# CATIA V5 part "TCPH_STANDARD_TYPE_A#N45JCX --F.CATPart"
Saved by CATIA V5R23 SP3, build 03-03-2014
Part number: TCPH_STANDARD_TYPE_A#N45JBE
Revision: --F
Nomenclature: _
Description: TCPH_STANDARD_TYPE_A
Property "MAT": "PR"
Property "Long Description": "CRYOP_HOUSING_UPPER_POSITION_C+GS"
Property "PBS Short": "3.1"
Property "VAC & FUEL CLASS": "N"
Property "GAS CLASS": "N"
Property "WATER CLASS": "N"
Property "ELEC CLASS": "N"
Property "CODAC CLASS": "N"
Property "RH CLASS": "N"
Property "HEAT CLASS": "N"
Property "DIAG CLASS": "N"
Property "CRYO CLASS": "N"
Property "NEU CLASS": "N"
Property "ASSY CLASS": "N"
Property "SAFETY CLASS": "N"
Property "QA CLASS": "N"
Property "DEPT": "_"
Property "DIVN": "_"
Property "GROUP": "_"
Property "UNIT": "_"
Property "PARTY": "_"
Property "RO": "---"
Property "RE": "SEKACHI"
Property "PRO": "---"
Property "Part Code": "TXT1"
Property "Part Origin": "ITER-P-3282KS+AA+-0"
Property "ITER Part Version": "-1"
Property "PBS Full Meaning": "VACUUM PUMPING"
Property "Date": "2005-11-11-09.18.13.000000"
Property "Responsible": "GLISSC"
Property "Site Resp": "SITE_AA"
Property "Organization": "ITER"
Property "Former PN": "ITER-P-3282KS"
Property "CHK MAT": "UNSYNC"
Property "PBS": "3.1 VACUUM PUMPING"
Property "Sig. Point Calc.": "N"
Property "ShortDescMig": "CRYOP_HOUSING_UPPER"
Property "PbsLevel1Mig": "31"
Property "PNMig": "235NFX"
Property "User In Enovia": "VAUQUEJ"
Property "Life Cycle Status": "Approved"
Property "ID": "N45JBE"
Property "AT": "PD"
Property "PBS 1": "24"
Property "PBS 2": "CR"
Property "PBS 3": "LC"
Property "LONG": "-"
Property "PREF": "Y"
Property "Change Type": "Minor"
Property "Maturity Level": "CD"
Property "Export Number": "_"
Property "REP": "CM"
Property "Object Type": "_"
Property "CADENAS_ID": "_"
Property "Description Modification": "DR-34 and DR-35"
Property "Description Documents": "_"
Property "BOM": "_"
Property "External Part ID": "ITER-C-235NEF"
Material "Stainless steel": density 8030 kg/m3, Young's modulus 2e+11 Pa, Poisson ratio 0.266, thermal expansion 1.17e-05 1/K
Bounding box of the stored display mesh (mm): x 13380 to 16870, y -1350 to 1350, z -6313 to -2983
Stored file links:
  C:\Users\pandeym\Desktop\__TCPH\TCPH_STANDARD_TYPE_A#N45JCX --F.CATPart
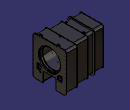
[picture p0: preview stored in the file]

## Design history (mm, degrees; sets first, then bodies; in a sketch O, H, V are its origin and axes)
Set1
  Line1 "CRYOPUMP_CENTER_AXIS": linked copy from another document
  DatumSurface1 "SURFACE_IN": linked copy from another document
  DatumSurface2 "SURFACE_OUT": linked copy from another document
  Sketch1 "TCPH_INNER_CYLINDER", origin (0, 0, 0), H (-1, 0, 0), V (0, 0, 1), geometry linked from another document
  Sketch2 "TCPH_VACUUM_PUMP_INTERFACE", origin (0, 0, 0), H (-1, 0, 0), V (0, 0, 1), geometry linked from another document
  Plane1 "CRYOPUMP_INTERFACE_PLANE_02": linked copy from another document
  Plane2 "CRYOPUMP_INTERFACE_PLANE_03": linked copy from another document
  Plane3 "CRYOPUMP_INTERFACE_PLANE_04": linked copy from another document
  Sketch3 "RH_RAIL_POCKETS", origin (15875, 0, 0), H (0, 1, 0), V (0, 0, 1), geometry linked from another document
  Sketch4 "CRYOPUMP_HOLES", origin (16720, 0, 0), H (0, 1, 0), V (0, 0, 1), geometry linked from another document
  Plane4 "CRYOPUMP_INTERFACE_PLANE_09": linked copy from another document
  Plane5 "CRYOPUMP_INTERFACE_PLANE_10": linked copy from another document
  Plane6 "CRYOPUMP_INTERFACE_PLANE_08": linked copy from another document
  Plane7 "CRYOPUMP_INTERFACE_PLANE_07": linked copy from another document
  Sketch5 "INNER_PLATES_HOLES", origin (15875, 0, 0), H (0, 1, 0), V (0, 0, 1), geometry linked from another document
  Sketch6 "SOCKET_PROFIL", origin (15540, 0, 0), H (0, 1, 0), V (0, 0, 1), geometry linked from another document
  Sketch7 "TCPH_SHELL_03", origin (14800, 0, 0), H (0, 1, 0), V (0, 0, 1), geometry linked from another document
  Sketch8 "TCPH_SHELL_02", origin (15855, 0, 0), H (0, 1, 0), V (0, 0, 1), geometry linked from another document
  Sketch9 "TCPH_SHELL_01", origin (16750, 0, 0), H (0, 1, 0), V (0, 0, 1), geometry linked from another document
  Sketch10 "TCPH_SHELL_04", origin (13400, 0, 0), H (0, 1, 0), V (0, 0, 1), geometry linked from another document
  Sketch11 "VERTICAL_PLATE_02", origin (14820, 0, 0), H (0, 1, 0), V (0, 0, 1), geometry linked from another document
  Sketch12 "VERTICAL_PLATE_01", origin (15855, 0, 0), H (0, 1, 0), V (0, 0, 1), geometry linked from another document
  Sketch13 "VERTICAL_PLATES_03", origin (13380, 0, 0), H (0, 1, 0), V (0, 0, 1), geometry linked from another document
  Sketch14 "INTERFACE_PLATE", origin (16800, 0, 0), H (0, 1, 0), V (0, 0, 1), geometry linked from another document
  Sketch15 "TCPH_FLANGE", origin (14800, 0, 0), H (0, 1, 0), V (0, 0, 1), geometry linked from another document
  DatumCurve1 "MONITORING_PIPE_PROFIL": linked copy from another document
  Sketch16 "LIFTING_PADS", origin (0, 0, -3193), H (1, 0, 0), V (0, 1, 0), geometry linked from another document
  Sketch17 "LIFTING_PADS_HOLES", origin (0, 0, -3193), H (1, 0, 0), V (0, 1, 0), geometry linked from another document
  Sketch18 "TEMPORARY_FLANGE_HOLES", origin (16800, 0, 0), H (0, 1, 0), V (0, 0, 1), geometry linked from another document
  Sketch19 "VACUUM_PIPE_SECTION_1", origin (0, 0, -6293), H (1, 0, 0), V (0, 1, 0), geometry linked from another document
  Sketch20 "RH_RAILS_HOLES", origin (16830, 0, 0), H (0, 1, 0), V (0, 0, 1), geometry linked from another document
  Sketch21 "RH_PINS", origin (15875, 0, 0), H (0, 1, 0), V (0, 0, 1), geometry linked from another document
  Sketch22 "RH_RAILS_INTERFACE", origin (16830, 0, 0), H (0, 1, 0), V (0, 0, 1), geometry linked from another document
  Sketch23 "PIS_TCPH_HOLES", origin (13380, 0, 0), H (0, 1, 0), V (0, 0, 1), geometry linked from another document
  Sketch24 "PIS_TCPH_PIPES", origin (13380, 0, 0), H (0, 1, 0), V (0, 0, 1), geometry linked from another document
  Sketch25 "FLANGE_DOCKING_PINS", origin (16800, 0, 0), H (0, 1, 0), V (0, 0, 1), geometry linked from another document
  Plane8 "TCPH_FRONT_LIMIT_PLANE_1": linked copy from another document
Set2
  Extract1: ExtractElem end face of Pad14
  Extract2: ExtractElem face of Pad14
  Extract3: ExtractElem face of Pad14
  Extract4: ExtractElem face of Pad14
  Join1: Elements (Extract1; Extract2; Extract3; Extract4)
Body1 "SHELL" (main body)
  Pad1: profile Sketch8, direction (1, 0, 0), up to start face of Pad9, opposite side up to Plane3
  Pad2: profile Sketch7, direction (1, 0, 0), up to DatumSurface2
  Pad3: profile Sketch9, direction (1, 0, 0), up to Plane2, opposite side up to end face of Pad5
  Pad4: profile Sketch10, direction (1, 0, 0), up to DatumSurface1
  Body2 "FLANGE"
    Solid1: linked copy from another document
  Remove1: tool Body2
  Sketch26 on face of Pad1, origin (0, 0, -6213), H (1, 0, 0), V (0, -1, 0)
    projected circle E1 centre (15565, 780) radius 77.04 from edge of Sketch19
  Pocket1: profile Sketch26, direction (0, 0, 1), through (limit type 6)
  Split1: SplitPlane Join1
Body3 "INTERFACE_PLATE"
  Pad5: profile Sketch14, direction (1, 0, 0), up to Plane1
  Shaft1: profile Sketch2, axis axis of face of Shaft2, angle 360
  Pad6: profile Sketch25, direction (1, 0, 0), length 70
  Chamfer1: length 15, angle 30, on edge [face of Pad6 | end face of Pad6] (x2)
  Sketch27 on face of Shaft1, origin (16800, -579.3117, -3160), H (0, 1, 0), V (0, 0, 1)
    point P1 (579.3117, -3)
    reference projected point E1 (579.3117, -3) from vertex of Sketch18
    coincidence: P1 E1
  Hole1: placed by Sketch27, at (16800, 0, -3163) direction (-1, 0, 0), diameter 22, through (limit type 3)
  UserPattern1: of Hole1, copies 49, at the points of Sketch18
  Sketch28 on face of Shaft1, origin (16720, -88.6401, -3549.6454), H (0, 1, 0), V (0, 0, 1)
    point P1 (-759.3599, -843.3546)
    reference projected point E1 (-759.3599, -843.3546) from vertex of Sketch4
    coincidence: E1 P1
  Hole2: placed by Sketch28, at (16720, -848, -4393) direction (-1, 0, 0), diameter 20.752, depth 80, V-bottom angle 120, threaded "M24", thread diameter 24, thread depth 70, pitch 3
  UserPattern2: of Hole2, copies 61, at the points of Sketch4
  Pocket2: profile Sketch23, direction (-1, 0, 0), up to face of Shaft1
  Pad7: profile Sketch22, direction (1, 0, 0), up to face of Shaft1
  Sketch29 on start face of Pad7, origin (16830, -750, -5093), H (0, 1, 0), V (0, 0, 1)
    point P1 (-50, 0)
    reference projected point E1 (-50, 0) from vertex of Sketch20
    coincidence: E1 P1
  Hole3: placed by Sketch29, at (16830, -800, -5093) direction (-1, 0, 0), diameter 13.835, up to face of Shaft1, threaded "M16", thread diameter 16, thread depth 30, pitch 2
  UserPattern3: of Hole3, copies 14, at the points of Sketch20
Body4 "VERTICAL_PLATES"
  Pad8: profile Sketch12, direction (1, 0, 0), up to Plane3, opposite side up to Plane2
  Pad9: profile Sketch11, direction (1, 0, 0), up to Plane6, opposite side up to Plane7
  Pad10: profile Sketch13, direction (1, 0, 0), up to Plane5, opposite side up to Plane4
  Pocket3: profile Sketch5, direction (-1, 0, 0), up to start face of Pad10
  Pocket4: profile Sketch23, direction (-1, 0, 0), through (limit type 3)
  Pocket5: profile Sketch34, direction (1, 0, 0), up to start face of Pad8
  Thickness1: Face face of Pocket4, Thickness -15
  Split2: SplitPlane Join1
  Thickness2: Face (face of Pocket4; face of Pocket4), Thickness -12.85
Body5 "FLANGE"
  Pad11: profile Sketch15, direction (1, 0, 0), up to DatumSurface1, opposite side up to DatumSurface2
  Pocket6: profile Sketch5, direction (-1, 0, 0), through (limit type 6)
  Sketch30 "PIS_TCPH_HOLES", origin (13380, 0, 0), H (0, 1, 0), V (0, 0, 1), geometry linked from another document
  Pocket7: profile Sketch30, direction (-1, 0, 0), through (limit type 3)
  Sketch31 on end face of Pad10, origin (13380, 0, 0), H (0, -1, 0), V (0, 0, 1)
    circle A1 centre (-990, -3363) radius 2
    point P1 (-990, -3363)
    construction line L1 (-990, -3257.5726) -> (-990, -3363)
    reference projected point E2 (-990, -3363) from vertex of DatumCurve1
    axis line L2 (-1097.0778, -3363) -> (-1024.3482, -3363)
    reference projected point E3 (-990, -3363) from vertex of DatumCurve1
    reference intersected line E4 through (0, 0) direction (0, -1) from zx-plane
    reference projected point E5 (-990, -3363) from vertex [face of DatumCurve1 | face of DatumCurve1]
    circle A2 centre (990, -3363) radius 2
    radius A1 = 2
    vertical: L1 V
    coincidence: L1 E2, L2 E3, P1 E5
    horizontal: L2 H
    symmetry: A1 A2 E4
  Sketch32 on end face of Pad10, origin (13380, 0, 0), H (0, -1, 0), V (0, 0, 1)
    circle A1 centre (-990, -3363) radius 3
    projected circle E2 centre (-990, -3363) radius 2 from edge [face of Pocket8 from Sketch31.A1 | end face of Pad11]
    reference intersected line E4 through (0, 0) direction (0, -1) from zx-plane
    circle A2 centre (990, -3363) radius 3
    circle A3 centre (990, -3363) radius 2
    distance E2 A1 = 1
    symmetry: A1 A2 E4, E2 A3 E4
    concentricity: E2 A1
  Pocket8: profile Sketch31, direction (1, 0, 0), through (limit type 3)
  Pad12: profile Sketch32, direction (1, 0, 0), length 885, opposite side length -765
  Thickness3: Face face of Pocket7, Thickness -15
  Thickness4: Face face of Pocket7, Thickness -12.85
Body6 "INNER_CYLINDER"
  Shaft2: profile Sketch1, axis Line1, angle 360
Body7 "POCKET"
  Pad13: profile Sketch6, direction (1, 0, 0), up to end face of Pad5
  Sketch33 on start face of Pad13, origin (15540, 0, 0), H (0, -1, 0), V (0, 0, 1)
    projected line E1 (-615, -6253) -> (-615, -5343) from edge of Sketch6
    projected line E2 (-615, -5343) -> (615, -5343) from edge of Sketch6
    projected line E3 (615, -5343) -> (615, -6253) from edge of Sketch6
    line L1 (-615, -6253) -> (615, -6253)
    horizontal: L1 H
  Pad14: profile Sketch33, direction (-1, 0, 0), length 20
  Pocket9: profile Sketch23, direction (1, 0, 0), up to face of Shaft1
Body8 "RH_POCKET"
  Pad15: profile Sketch3, direction (1, 0, 0), up to end face of Pad5, opposite side length 50
  Sketch34 on start face of Pad15, origin (15825, 0, 0), H (0, 1, 0), V (0, 0, 1)
    projected line E2 (-645, -5184.7157) -> (-736.7157, -5093) from edge of Sketch3
    projected line E3 (-736.7157, -5093) -> (-970, -5093) from edge of Sketch3
    projected line E4 (-970, -5093) -> (-970, -5468) from edge of Sketch3
    projected line E5 (-970, -5468) -> (-645, -5468) from edge of Sketch3
    projected line E6 (736.7157, -5093) -> (645, -5184.7157) from edge of Sketch3
    projected line E7 (970, -5093) -> (736.7157, -5093) from edge of Sketch3
    projected line E8 (970, -5468) -> (970, -5093) from edge of Sketch3
    projected line E9 (645, -5468) -> (970, -5468) from edge of Sketch3
    projected point E10 (0, -4393) from axis of face of Shaft2
    projected line E11 (645, -5184.7157) -> (645, -5468) from edge of Sketch3
    projected line E12 (-645, -5468) -> (-645, -5184.7157) from edge of Sketch3
  Pad16: profile Sketch34, direction (-1, 0, 0), length 20
  Body9 "POCKET"
    Solid2: linked copy from another document
  Remove2: tool Body9
  Pad17: profile Sketch21, direction (1, 0, 0), up to start face of Pad16
  Chamfer2: length 20, angle 30, on edge [face of Pad17 | start face of Pad17] (x2)
Body10 "TUBE_B1_TO_B5"
  Pad18: profile Sketch24, direction (-1, 0, 0), up to end face of Pad10, opposite side up to face of Shaft1
  Thickness5: Face start face of Pad18, Thickness -1160
Body11 "VACUUM_PIPE"
  Pad19: profile Sketch19, direction (0, 0, 1), length 80
Body12 "LIFTING_PADS"
  Pad20: profile Sketch16, direction (0, 0, 1), length 60
  Sketch35 on end face of Pad20, origin (15830, 0, -3133), H (1, 0, 0), V (0, 1, 0)
    point P1 (100, 0)
    reference projected point E1 (100, 0) from vertex of Sketch17
    coincidence: E1 P1
  Hole4: placed by Sketch35, at (15930, 0, -3133) direction (0, 0, -1), diameter 31.67, through (limit type 3), threaded "M36", thread diameter 36, thread depth 60, pitch 4
  UserPattern4: of Hole4, copies 3, at the points of Sketch17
